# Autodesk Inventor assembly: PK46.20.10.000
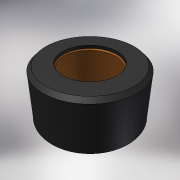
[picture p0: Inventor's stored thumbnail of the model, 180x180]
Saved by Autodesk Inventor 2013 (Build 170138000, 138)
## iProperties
Created: 2012-02
Part Number: PK46.20.10.000
Document SubType Name: Assembly
Designer: tedescj
Author: tedescj
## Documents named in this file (3)
- C:\Product Design Suite 2013 Test Drive\Dynamic Simulation\Workspace\Assy, Chassis, Front\PK46.20.10.000.iam
- C:\Product Design Suite 2013 Test Drive\Dynamic Simulation\Workspace\Assy, Chassis, Front\PK46.20.11.000.ipt
- C:\Product Design Suite 2013 Test Drive\Dynamic Simulation\Workspace\Assy, Chassis, Front\PK46.20.12.000.ipt
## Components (2 placed, 2 different names)
1. PK46.20.11.000:1
2. PK46.20.12.000:1
